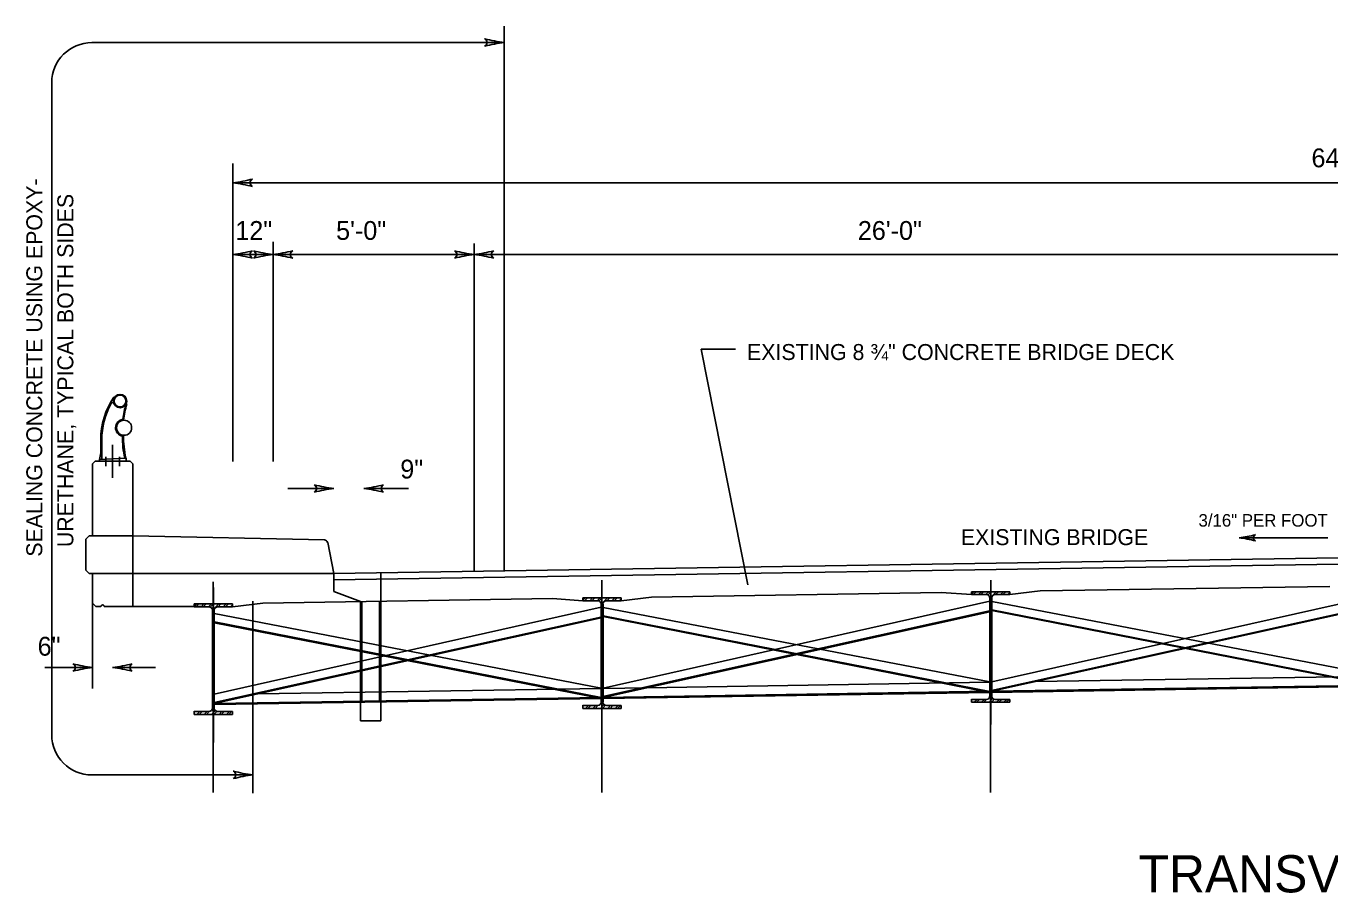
# Model space of a CAD drawing. Extents: x 10803 to 14007, y 6159 to 7440.
# Drawn here: x 13618.12 to 13650.54, y 6284.31 to 6305.88 of the extents above; entities that cross this region are included whole.
import ezdxf

# ---------------------------------------------------------------- set-up
doc = ezdxf.new("R2010")
doc.units = 0
for name, color, linetype in [('BR_P_Slab_Object', 7, 'Continuous'), ('BR_X_Rail_Object', 7, 'Continuous'), ('BR_X_Slab_Const_Joint', 7, 'Continuous'), ('BR_X_Slab_Object', 7, 'Continuous'), ('Default', 7, 'Continuous')]:
    doc.layers.add(name, color=color, linetype=linetype)

# ---------------------------------------------------------------- blocks, each defined once
blk = doc.blocks.new('LT2')
at = {"layer": 'Default'}
blk.add_line((-0.163, 0.031), (-0.163, 0.031), dxfattribs=at)
for centre, start, end in [((0.147, 1.218), 255.3829, 263.1374), ((0.147, -1.218), 96.8626, 104.6171)]:
    blk.add_arc(centre, 1.227, start, end, dxfattribs=at)
blk.add_ellipse((-0.185, 0), major_axis=(0.0415, 0), ratio=0.873734, start_param=5.258637, end_param=7.300638, dxfattribs=at)

msp = doc.modelspace()

# ---------------------------------------------------------------- linework, layer by layer
at = {"layer": 'BR_P_Slab_Object'}
for p, q in [((13620.774, 6293.198), (13625.541, 6293.095)), ((13620.774, 6293.198), (13620.774, 6291.436)), ((13625.621, 6293.028), (13625.774, 6292.26)), ((13651.774, 6292.666), (13625.774, 6292.26)), ((13650.545, 6291.939), (13643.339, 6291.826)), ((13631.214, 6291.637), (13624.006, 6291.524)), ((13631.214, 6291.637), (13631.964, 6291.583)), ((13632.923, 6291.583), (13633.672, 6291.675)), ((13640.881, 6291.788), (13633.672, 6291.675)), ((13640.881, 6291.788), (13641.631, 6291.734)), ((13642.589, 6291.734), (13643.339, 6291.826)), ((13620.774, 6291.436), (13622.298, 6291.432)), ((13623.257, 6291.432), (13624.006, 6291.524))]:
    msp.add_line(p, q, dxfattribs=at)
msp.add_arc((13625.539, 6293.012), 0.0833, 11.3099, 88.7673, dxfattribs=at)
at = {"layer": 'BR_X_Rail_Object'}
for p, q in [((13620.318, 6296.638), (13620.299, 6296.648)), ((13620.626, 6296.472), (13620.607, 6296.478)), ((13619.976, 6295.582), (13619.976, 6295.265)), ((13620.002, 6295.584), (13620.002, 6295.098)), ((13619.943, 6295.094), (13620.606, 6295.133)), ((13620.606, 6295.133), (13620.606, 6295.051)), ((13619.943, 6295.094), (13619.943, 6295.051))]:
    msp.add_line(p, q, dxfattribs=at)
for centre, radius in [((13620.458, 6296.551), 0.166), ((13620.458, 6296.551), 0.146), ((13620.559, 6295.885), 0.187)]:
    msp.add_circle(centre, radius, dxfattribs=at)
for centre, radius, start, end in [((13621.893, 6295.584), 1.916, 146.2879, 180.0713), ((13621.893, 6295.584), 1.89, 151.3488, 180.0713), ((13620.269, 6296.471), 0.0394, 22.735, 151.3488), ((13622.677, 6295.841), 2.165, 162.8878, 173.1781), ((13622.677, 6295.841), 2.146, 162.8878, 173.8469), ((13620.559, 6295.885), 0.213, 98.8055, 259.1055), ((13622.71, 6295.635), 2.192, 178.9792, 193.4258), ((13622.71, 6295.635), 2.165, 178.3406, 193.4258), ((13619.477, 6295.271), 0.499, 339.2463, 359.3787)]:
    msp.add_arc(centre, radius, start, end, dxfattribs=at)
at = {"layer": 'BR_X_Slab_Const_Joint'}
for p, q in [((13620.774, 6293.198), (13619.774, 6293.198)), ((13625.774, 6292.26), (13619.774, 6292.26))]:
    msp.add_line(p, q, dxfattribs=at)
at = {"layer": 'BR_X_Slab_Object'}
for p, q in [((13619.774, 6294.989), (13619.837, 6295.051)), ((13619.774, 6294.989), (13619.774, 6293.198)), ((13619.837, 6295.051), (13620.712, 6295.051)), ((13620.774, 6294.989), (13620.712, 6295.051)), ((13620.774, 6294.989), (13620.774, 6293.198)), ((13619.691, 6293.198), (13619.608, 6293.114)), ((13619.774, 6293.198), (13619.691, 6293.198)), ((13619.608, 6293.114), (13619.608, 6292.344)), ((13619.608, 6292.344), (13619.691, 6292.26)), ((13619.774, 6292.26), (13619.691, 6292.26)), ((13619.774, 6292.26), (13619.774, 6291.519)), ((13651.774, 6292.508), (13625.774, 6292.101)), ((13625.774, 6292.101), (13625.774, 6292.26)), ((13619.858, 6291.436), (13619.774, 6291.519)), ((13619.984, 6291.436), (13619.858, 6291.436)), ((13622.555, 6291.436), (13620.066, 6291.436))]:
    msp.add_line(p, q, dxfattribs=at)
msp.add_arc((13620.024, 6291.436), 0.0417, 359.9982, 180, dxfattribs=at)
at = {"layer": 'Default'}
for p, q in [((13630.014, 6292.315), (13630.014, 6305.877)), ((13629.526, 6305.561), (13629.525, 6305.561)), ((13630.014, 6305.468), (13619.76, 6305.468)), ((13618.76, 6304.468), (13618.76, 6288.251)), ((13623.264, 6295.044), (13623.264, 6302.456)), ((13623.264, 6301.979), (13680.285, 6301.979)), ((13623.752, 6301.886), (13623.753, 6301.886)), ((13624.264, 6295.044), (13624.264, 6300.514)), ((13629.264, 6292.315), (13629.264, 6300.469)), ((13623.264, 6300.196), (13624.264, 6300.196)), ((13623.752, 6300.103), (13623.753, 6300.103)), ((13623.776, 6300.289), (13623.775, 6300.289)), ((13624.264, 6300.196), (13629.264, 6300.196)), ((13624.752, 6300.103), (13624.753, 6300.103)), ((13628.776, 6300.289), (13628.775, 6300.289)), ((13629.264, 6300.196), (13651.774, 6300.196)), ((13629.752, 6300.103), (13629.753, 6300.103)), ((13636.072, 6291.982), (13634.913, 6297.838)), ((13634.913, 6297.838), (13635.759, 6297.838)), ((13620.274, 6295.463), (13620.274, 6294.64)), ((13620.107, 6295.16), (13620.107, 6294.927)), ((13620.442, 6295.16), (13620.442, 6294.933)), ((13625.774, 6294.374), (13624.632, 6294.374)), ((13625.286, 6294.467), (13625.285, 6294.467)), ((13626.524, 6294.374), (13627.629, 6294.374)), ((13627.012, 6294.282), (13627.013, 6294.282)), ((13648.285, 6293.149), (13650.491, 6293.149)), ((13626.94, 6290.4), (13626.94, 6292.279)), ((13622.774, 6292.05), (13622.774, 6286.816)), ((13622.778, 6291.912), (13622.778, 6288.053)), ((13625.774, 6291.814), (13625.774, 6292.101)), ((13632.441, 6292.091), (13632.441, 6286.816)), ((13632.443, 6292.05), (13632.443, 6288.19)), ((13642.11, 6292.091), (13642.11, 6288.502)), ((13623.764, 6291.574), (13623.764, 6286.796)), ((13625.774, 6291.814), (13626.44, 6291.562)), ((13626.44, 6291.562), (13626.44, 6290.512)), ((13626.472, 6290.505), (13626.472, 6291.563)), ((13626.909, 6291.57), (13626.909, 6290.407)), ((13631.964, 6291.583), (13631.964, 6291.656)), ((13631.964, 6291.656), (13632.923, 6291.656)), ((13631.964, 6291.594), (13632.026, 6291.656)), ((13632.336, 6291.583), (13631.964, 6291.583)), ((13632.01, 6291.583), (13632.083, 6291.656)), ((13632.137, 6291.583), (13632.21, 6291.656)), ((13632.194, 6291.583), (13632.267, 6291.656)), ((13632.321, 6291.583), (13632.394, 6291.656)), ((13632.336, 6291.583), (13632.336, 6291.583)), ((13632.368, 6291.574), (13632.45, 6291.656)), ((13632.419, 6291.498), (13632.578, 6291.656)), ((13642.086, 6291.571), (13632.468, 6289.412)), ((13632.923, 6291.583), (13632.551, 6291.583)), ((13632.561, 6291.583), (13632.634, 6291.656)), ((13632.689, 6291.583), (13632.762, 6291.656)), ((13632.745, 6291.583), (13632.818, 6291.656)), ((13632.872, 6291.583), (13632.923, 6291.633)), ((13632.923, 6291.656), (13632.923, 6291.583)), ((13641.631, 6291.734), (13641.631, 6291.807)), ((13641.631, 6291.807), (13642.589, 6291.807)), ((13641.631, 6291.745), (13641.693, 6291.807)), ((13642.003, 6291.734), (13641.631, 6291.734)), ((13641.676, 6291.734), (13641.749, 6291.807)), ((13641.804, 6291.734), (13641.877, 6291.807)), ((13641.86, 6291.734), (13641.933, 6291.807)), ((13641.988, 6291.734), (13642.06, 6291.807)), ((13642.003, 6291.734), (13642.003, 6291.734)), ((13642.035, 6291.725), (13642.117, 6291.807)), ((13642.086, 6291.649), (13642.244, 6291.807)), ((13642.086, 6289.213), (13642.086, 6291.651)), ((13642.086, 6291.592), (13642.134, 6291.64)), ((13651.753, 6291.723), (13642.134, 6289.564)), ((13642.134, 6291.651), (13642.134, 6289.213)), ((13651.753, 6289.713), (13642.134, 6291.568)), ((13642.589, 6291.734), (13642.218, 6291.734)), ((13642.228, 6291.734), (13642.301, 6291.807)), ((13642.355, 6291.734), (13642.428, 6291.807)), ((13642.412, 6291.734), (13642.485, 6291.807)), ((13642.539, 6291.734), (13642.589, 6291.784)), ((13642.589, 6291.807), (13642.589, 6291.734)), ((13619.774, 6291.519), (13619.774, 6289.4)), ((13622.298, 6291.432), (13622.298, 6291.505)), ((13622.298, 6291.505), (13623.257, 6291.505)), ((13622.298, 6291.443), (13622.36, 6291.505)), ((13622.67, 6291.432), (13622.298, 6291.432)), ((13622.344, 6291.432), (13622.417, 6291.505)), ((13622.471, 6291.432), (13622.544, 6291.505)), ((13622.528, 6291.432), (13622.601, 6291.505)), ((13622.655, 6291.432), (13622.728, 6291.505)), ((13622.67, 6291.432), (13622.67, 6291.432)), ((13622.703, 6291.423), (13622.785, 6291.505)), ((13622.753, 6291.347), (13622.912, 6291.505)), ((13622.753, 6288.911), (13622.753, 6291.349)), ((13622.753, 6291.29), (13622.802, 6291.338)), ((13632.42, 6291.42), (13622.802, 6289.261)), ((13622.802, 6291.349), (13622.802, 6288.911)), ((13632.42, 6289.411), (13622.802, 6291.265)), ((13623.257, 6291.432), (13622.885, 6291.432)), ((13622.895, 6291.432), (13622.968, 6291.505)), ((13623.023, 6291.432), (13623.096, 6291.505)), ((13623.079, 6291.432), (13623.152, 6291.505)), ((13623.207, 6291.432), (13623.257, 6291.482)), ((13623.257, 6291.505), (13623.257, 6291.432)), ((13632.419, 6289.062), (13632.419, 6291.5)), ((13632.419, 6291.441), (13632.468, 6291.489)), ((13632.419, 6291.314), (13632.468, 6291.362)), ((13632.419, 6291.257), (13632.468, 6291.306)), ((13632.463, 6289.2), (13642.081, 6291.328)), ((13632.468, 6291.5), (13632.468, 6289.062)), ((13642.086, 6289.562), (13632.468, 6291.416)), ((13632.468, 6289.179), (13642.086, 6291.307)), ((13642.086, 6291.465), (13642.134, 6291.513)), ((13642.086, 6291.408), (13642.134, 6291.457)), ((13642.086, 6291.281), (13642.134, 6291.329)), ((13642.086, 6291.224), (13642.134, 6291.273)), ((13642.13, 6289.351), (13651.748, 6291.479)), ((13642.134, 6289.33), (13651.753, 6291.458)), ((13651.753, 6289.455), (13642.134, 6291.339)), ((13651.753, 6289.476), (13642.138, 6291.359)), ((13622.753, 6291.163), (13622.802, 6291.211)), ((13622.753, 6291.106), (13622.802, 6291.155)), ((13622.753, 6290.979), (13622.802, 6291.027)), ((13622.753, 6290.922), (13622.802, 6290.971)), ((13622.797, 6289.049), (13632.416, 6291.177)), ((13622.802, 6289.028), (13632.42, 6291.156)), ((13632.42, 6289.153), (13622.802, 6291.037)), ((13632.42, 6289.174), (13622.806, 6291.057)), ((13632.419, 6291.13), (13632.468, 6291.178)), ((13632.419, 6291.073), (13632.468, 6291.122)), ((13632.419, 6290.946), (13632.468, 6290.994)), ((13632.419, 6290.889), (13632.468, 6290.938)), ((13642.086, 6289.304), (13632.468, 6291.188)), ((13642.086, 6289.325), (13632.472, 6291.208)), ((13642.086, 6291.097), (13642.134, 6291.145)), ((13642.086, 6291.041), (13642.134, 6291.089)), ((13642.086, 6290.913), (13642.134, 6290.962)), ((13622.753, 6290.795), (13622.802, 6290.843)), ((13622.753, 6290.738), (13622.802, 6290.787)), ((13622.753, 6290.611), (13622.802, 6290.66)), ((13622.753, 6290.555), (13622.802, 6290.603)), ((13632.419, 6290.762), (13632.468, 6290.811)), ((13632.419, 6290.706), (13632.468, 6290.754)), ((13632.419, 6290.578), (13632.468, 6290.627)), ((13642.086, 6290.857), (13642.134, 6290.905)), ((13642.086, 6290.729), (13642.134, 6290.778)), ((13642.086, 6290.673), (13642.134, 6290.721)), ((13642.086, 6290.546), (13642.134, 6290.594)), ((13642.108, 6290.872), (13642.108, 6286.816)), ((13622.753, 6290.427), (13622.802, 6290.476)), ((13622.753, 6290.371), (13622.802, 6290.419)), ((13622.753, 6290.244), (13622.802, 6290.292)), ((13626.44, 6290.254), (13626.44, 6290.512)), ((13626.472, 6290.247), (13626.472, 6290.505)), ((13626.909, 6289.988), (13626.909, 6290.407)), ((13626.94, 6289.996), (13626.94, 6290.4)), ((13632.419, 6290.522), (13632.468, 6290.57)), ((13632.419, 6290.395), (13632.468, 6290.443)), ((13632.419, 6290.338), (13632.468, 6290.386)), ((13632.419, 6290.211), (13632.468, 6290.259)), ((13642.086, 6290.489), (13642.134, 6290.537)), ((13642.086, 6290.362), (13642.134, 6290.41)), ((13642.086, 6290.305), (13642.134, 6290.354)), ((13619.286, 6290.015), (13619.285, 6290.015)), ((13622.753, 6290.187), (13622.802, 6290.235)), ((13622.753, 6290.06), (13622.802, 6290.108)), ((13622.753, 6290.003), (13622.802, 6290.051)), ((13626.44, 6290.128), (13626.44, 6290.254)), ((13626.44, 6289.868), (13626.44, 6290.128)), ((13626.472, 6290.247), (13626.472, 6290.136)), ((13626.472, 6289.876), (13626.472, 6290.136)), ((13626.909, 6289.988), (13626.909, 6289.316)), ((13626.94, 6289.316), (13626.94, 6289.996)), ((13632.419, 6290.154), (13632.468, 6290.202)), ((13632.419, 6290.027), (13632.468, 6290.075)), ((13632.419, 6289.97), (13632.468, 6290.019)), ((13642.086, 6290.178), (13642.134, 6290.226)), ((13642.086, 6290.121), (13642.134, 6290.17)), ((13642.086, 6289.994), (13642.134, 6290.042)), ((13642.086, 6289.937), (13642.134, 6289.986)), ((13619.774, 6289.922), (13618.591, 6289.922)), ((13620.274, 6289.922), (13621.339, 6289.922)), ((13620.762, 6289.829), (13620.763, 6289.829)), ((13622.753, 6289.876), (13622.802, 6289.924)), ((13622.753, 6289.819), (13622.802, 6289.868)), ((13622.753, 6289.692), (13622.802, 6289.74)), ((13622.753, 6289.635), (13622.802, 6289.684)), ((13626.44, 6289.868), (13626.44, 6289.309)), ((13626.472, 6289.309), (13626.472, 6289.876)), ((13632.419, 6289.843), (13632.468, 6289.891)), ((13632.419, 6289.786), (13632.468, 6289.835)), ((13632.419, 6289.659), (13632.468, 6289.707)), ((13632.419, 6289.603), (13632.468, 6289.651)), ((13642.086, 6289.81), (13642.134, 6289.859)), ((13642.086, 6289.754), (13642.134, 6289.802)), ((13642.086, 6289.626), (13642.134, 6289.675)), ((13642.086, 6289.57), (13642.134, 6289.618)), ((13643.22, 6289.57), (13651.753, 6289.705)), ((13622.753, 6289.508), (13622.802, 6289.556)), ((13622.753, 6289.452), (13622.802, 6289.5)), ((13622.753, 6289.324), (13622.802, 6289.373)), ((13622.753, 6289.268), (13622.802, 6289.316)), ((13623.887, 6289.268), (13632.42, 6289.403)), ((13626.44, 6289.059), (13626.44, 6289.309)), ((13626.472, 6289.059), (13626.472, 6289.309)), ((13626.909, 6289.066), (13626.909, 6289.316)), ((13626.94, 6289.066), (13626.94, 6289.316)), ((13631.376, 6289.386), (13632.419, 6289.152)), ((13632.419, 6289.475), (13632.468, 6289.524)), ((13632.419, 6289.419), (13632.468, 6289.467)), ((13632.419, 6289.291), (13632.468, 6289.34)), ((13632.468, 6289.402), (13633.553, 6289.42)), ((13632.468, 6289.178), (13642.086, 6289.33)), ((13632.471, 6289.152), (13642.086, 6289.304)), ((13633.553, 6289.419), (13642.086, 6289.554)), ((13642.086, 6289.443), (13642.134, 6289.491)), ((13642.086, 6289.386), (13642.134, 6289.434)), ((13642.086, 6289.259), (13642.134, 6289.307)), ((13642.134, 6289.33), (13651.753, 6289.481)), ((13642.138, 6289.303), (13651.753, 6289.455)), ((13622.753, 6289.14), (13622.802, 6289.189)), ((13622.753, 6289.084), (13622.802, 6289.132)), ((13622.753, 6288.957), (13622.802, 6289.005)), ((13622.802, 6289.027), (13632.42, 6289.179)), ((13622.805, 6289.001), (13632.42, 6289.153)), ((13626.44, 6289.059), (13626.44, 6288.592)), ((13626.94, 6288.592), (13626.94, 6289.066)), ((13631.964, 6288.906), (13631.964, 6288.986)), ((13631.964, 6288.979), (13632.336, 6288.979)), ((13631.964, 6288.964), (13631.979, 6288.979)), ((13632.034, 6288.906), (13632.107, 6288.979)), ((13632.09, 6288.906), (13632.163, 6288.979)), ((13632.218, 6288.906), (13632.291, 6288.979)), ((13632.274, 6288.906), (13632.351, 6288.983)), ((13632.402, 6288.906), (13632.497, 6289.001)), ((13632.418, 6289.049), (13632.468, 6289.099)), ((13632.419, 6289.235), (13632.468, 6289.283)), ((13632.419, 6289.108), (13632.468, 6289.156)), ((13632.458, 6288.906), (13632.534, 6288.982)), ((13632.551, 6288.979), (13632.923, 6288.979)), ((13632.585, 6288.906), (13632.658, 6288.979)), ((13632.642, 6288.906), (13632.715, 6288.979)), ((13632.769, 6288.906), (13632.842, 6288.979)), ((13632.826, 6288.906), (13632.899, 6288.979)), ((13632.923, 6288.979), (13632.923, 6288.906)), ((13641.631, 6289.057), (13641.631, 6289.137)), ((13641.631, 6289.13), (13642.003, 6289.13)), ((13641.631, 6289.115), (13641.646, 6289.13)), ((13642.589, 6289.057), (13641.631, 6289.057)), ((13641.7, 6289.057), (13641.773, 6289.13)), ((13641.757, 6289.057), (13641.83, 6289.13)), ((13641.884, 6289.057), (13641.957, 6289.13)), ((13641.941, 6289.057), (13642.017, 6289.134)), ((13642.068, 6289.057), (13642.163, 6289.152)), ((13642.084, 6289.201), (13642.134, 6289.25)), ((13642.125, 6289.057), (13642.201, 6289.133)), ((13642.218, 6289.13), (13642.589, 6289.13)), ((13642.252, 6289.057), (13642.325, 6289.13)), ((13642.309, 6289.057), (13642.382, 6289.13)), ((13642.436, 6289.057), (13642.509, 6289.13)), ((13642.492, 6289.057), (13642.565, 6289.13)), ((13642.589, 6289.13), (13642.589, 6289.057)), ((13622.298, 6288.755), (13622.298, 6288.835)), ((13622.298, 6288.828), (13622.67, 6288.828)), ((13622.298, 6288.813), (13622.314, 6288.828)), ((13623.257, 6288.755), (13622.298, 6288.755)), ((13622.368, 6288.755), (13622.441, 6288.828)), ((13622.425, 6288.755), (13622.497, 6288.828)), ((13622.552, 6288.755), (13622.625, 6288.828)), ((13622.608, 6288.755), (13622.685, 6288.832)), ((13622.736, 6288.755), (13622.831, 6288.85)), ((13622.752, 6288.898), (13622.802, 6288.948)), ((13622.792, 6288.755), (13622.868, 6288.831)), ((13622.885, 6288.828), (13623.257, 6288.828)), ((13622.92, 6288.755), (13622.992, 6288.828)), ((13622.976, 6288.755), (13623.049, 6288.828)), ((13623.103, 6288.755), (13623.176, 6288.828)), ((13623.16, 6288.755), (13623.233, 6288.828)), ((13623.257, 6288.828), (13623.257, 6288.755)), ((13632.923, 6288.906), (13631.964, 6288.906)), ((13626.44, 6288.592), (13626.94, 6288.592)), ((13623.276, 6287.344), (13623.275, 6287.344)), ((13619.76, 6287.251), (13623.764, 6287.251))]:
    msp.add_line(p, q, dxfattribs=at)
for centre, radius, start, end in [((13630.454, 6309.122), 3.68, 255.3829, 263.1374), ((13619.76, 6304.468), 1, 90, 180), ((13630.454, 6301.815), 3.68, 96.8626, 104.6171), ((13622.824, 6305.633), 3.68, 276.8626, 284.6171), ((13622.824, 6298.325), 3.68, 75.3829, 83.1374), ((13622.824, 6303.85), 3.68, 276.8626, 284.6171), ((13622.824, 6296.542), 3.68, 75.3829, 83.1374), ((13624.704, 6303.85), 3.68, 255.3829, 263.1374), ((13624.704, 6296.542), 3.68, 96.8626, 104.6171), ((13623.824, 6303.85), 3.68, 276.8626, 284.6171), ((13623.824, 6296.542), 3.68, 75.3829, 83.1374), ((13629.704, 6303.85), 3.68, 255.3829, 263.1374), ((13629.704, 6296.542), 3.68, 96.8626, 104.6171), ((13628.824, 6303.85), 3.68, 276.8626, 284.6171), ((13628.824, 6296.542), 3.68, 75.3829, 83.1374), ((13626.214, 6298.028), 3.68, 255.3829, 263.1374), ((13626.214, 6290.72), 3.68, 96.8626, 104.6171), ((13626.084, 6298.028), 3.68, 276.8626, 284.6171), ((13626.084, 6290.72), 3.68, 75.3829, 83.1374), ((13632.336, 6291.5), 0.0833, 0, 90), ((13632.551, 6291.5), 0.0833, 90, 180), ((13642.003, 6291.651), 0.0833, 0, 90), ((13642.218, 6291.651), 0.0833, 90, 180), ((13622.67, 6291.349), 0.0833, 0, 90), ((13622.885, 6291.349), 0.0833, 90, 180), ((13620.214, 6293.576), 3.68, 255.3829, 263.1374), ((13619.834, 6293.576), 3.68, 276.8626, 284.6171), ((13620.214, 6286.268), 3.68, 96.8626, 104.6171), ((13619.834, 6286.268), 3.68, 75.3829, 83.1374), ((13632.336, 6289.062), 0.0833, 270, 360), ((13632.551, 6289.062), 0.0833, 180, 270), ((13642.003, 6289.213), 0.0833, 270, 360), ((13642.218, 6289.213), 0.0833, 180, 270), ((13622.67, 6288.911), 0.0833, 270, 360), ((13622.885, 6288.911), 0.0833, 180, 270), ((13619.76, 6288.251), 1, 180, 270), ((13624.204, 6290.905), 3.68, 255.3829, 263.1374), ((13624.204, 6283.597), 3.68, 96.8626, 104.6171)]:
    msp.add_arc(centre, radius, start, end, dxfattribs=at)
for centre, major_axis in [((13629.46, 6305.469), (0.125, 0)), ((13623.818, 6301.979), (-0.125, 0)), ((13623.818, 6300.196), (-0.125, 0)), ((13623.71, 6300.196), (0.125, 0)), ((13624.818, 6300.196), (-0.125, 0)), ((13628.71, 6300.196), (0.125, 0)), ((13629.818, 6300.196), (-0.125, 0)), ((13625.22, 6294.375), (0.125, 0)), ((13627.078, 6294.374), (-0.125, 0)), ((13619.221, 6289.922), (0.125, 0)), ((13620.828, 6289.922), (-0.125, 0)), ((13623.21, 6287.251), (0.125, 0))]:
    msp.add_ellipse(centre, major_axis=major_axis, ratio=0.873734, start_param=5.258637, end_param=7.300638, dxfattribs=at)

# ---------------------------------------------------------------- block references
at = {"layer": 'Default', "xscale": 2.499995, "yscale": 2.499995, "rotation": 180}
msp.add_blockref('LT2', (13648.285, 6293.149), dxfattribs=at)

# ---------------------------------------------------------------- texts
at = {"layer": 'Default'}
for s, height, p in [('64\'-0" C/C', 0.468, (13650.086, 6302.365)), ('12"', 0.468, (13623.324, 6300.559)), ('5\'-0"', 0.468, (13625.831, 6300.559)), ('26\'-0"', 0.468, (13638.805, 6300.559)), ('EXISTING 8 ¾" CONCRETE BRIDGE DECK', 0.39687, (13636.049, 6297.571)), ('9"', 0.468, (13627.427, 6294.624)), ('3/16" PER FOOT', 0.3125, (13647.277, 6293.426)), ('EXISTING BRIDGE', 0.39687, (13641.367, 6292.966)), ('6"', 0.468, (13618.408, 6290.217)), ('TRANSVERSE SECTION', 0.92604, (13645.787, 6284.328))]:
    msp.add_text(s, height=height, dxfattribs=at).set_placement(p)
for s, p in [('SEALING CONCRETE USING EPOXY-', (13618.524, 6292.679)), ('URETHANE, TYPICAL BOTH SIDES', (13619.296, 6292.916))]:
    msp.add_text(s, height=0.39687, rotation=90, dxfattribs=at).set_placement(p)

doc.saveas('drawing.dxf')
